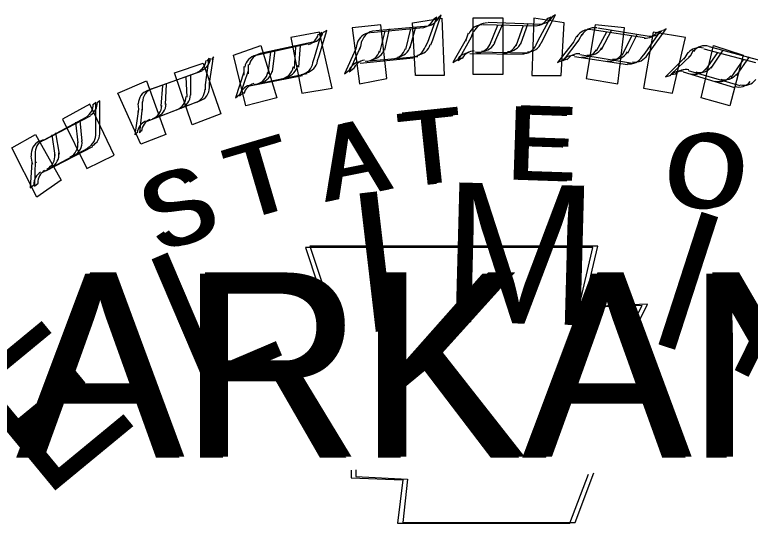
# Model space of a CAD drawing. Extents: x -1771525.9 to -1771483.9, y -422628.9 to -422606.9.
# Drawn here: x -1771500.66 to -1771499.911, y -422625.924 to -422625.405 of the extents above; entities that cross this region are included whole.
import ezdxf

# ---------------------------------------------------------------- set-up
doc = ezdxf.new("R2010")
doc.units = 0
for name, color, linetype in [('Border 2660-Hwy18 - STAMP PRELIM', 7, 'Continuous'), ('Border 2660-Hwy18 - Stamp-ChrisC', 7, 'Continuous'), ('Stamp Charles W', 7, 'Continuous')]:
    doc.layers.add(name, color=color, linetype=linetype)

msp = doc.modelspace()

# ---------------------------------------------------------------- linework, layer by layer
at = {"layer": 'Border 2660-Hwy18 - STAMP PRELIM'}
for p, q in [((-1771500.25546, -422625.41348), (-1771500.22546, -422625.40898)), ((-1771500.25246, -422625.46748), (-1771500.25546, -422625.41348)), ((-1771500.22546, -422625.40898), (-1771500.22316, -422625.46748)), ((-1771500.16316, -422625.40898), (-1771500.19396, -422625.40898)), ((-1771500.19396, -422625.40898), (-1771500.19396, -422625.46598)), ((-1771500.16316, -422625.46598), (-1771500.16316, -422625.40898)), ((-1771500.13166, -422625.40898), (-1771500.13396, -422625.46748)), ((-1771500.10096, -422625.41348), (-1771500.13166, -422625.40898)), ((-1771500.10396, -422625.46748), (-1771500.10096, -422625.41348)), ((-1771500.28766, -422625.41568), (-1771500.31696, -422625.41868)), ((-1771500.31696, -422625.41868), (-1771500.30946, -422625.47568)), ((-1771500.28166, -422625.47048), (-1771500.28766, -422625.41568)), ((-1771500.06946, -422625.41568), (-1771500.07846, -422625.47048)), ((-1771500.03946, -422625.41868), (-1771500.06946, -422625.41568)), ((-1771500.04616, -422625.47568), (-1771500.03946, -422625.41868)), ((-1771500.34996, -422625.42318), (-1771500.37916, -422625.42848)), ((-1771500.37916, -422625.42848), (-1771500.36796, -422625.48548)), ((-1771500.33716, -422625.48018), (-1771500.34996, -422625.42318)), ((-1771500.01016, -422625.42318), (-1771500.01996, -422625.48018)), ((-1771499.97716, -422625.42848), (-1771500.01016, -422625.42318)), ((-1771499.99066, -422625.48548), (-1771499.97716, -422625.42848)), ((-1771500.43766, -422625.44648), (-1771500.40996, -422625.43668)), ((-1771500.40996, -422625.43668), (-1771500.39346, -422625.48998)), ((-1771499.96146, -422625.48998), (-1771499.94866, -422625.43668)), ((-1771499.94866, -422625.43668), (-1771499.91866, -422625.44648)), ((-1771500.42496, -422625.49818), (-1771500.43766, -422625.44648)), ((-1771499.91866, -422625.44648), (-1771499.93216, -422625.49818)), ((-1771500.49766, -422625.46448), (-1771500.46846, -422625.45468)), ((-1771500.46846, -422625.45468), (-1771500.45046, -422625.50648)), ((-1771500.47966, -422625.51768), (-1771500.49766, -422625.46448)), ((-1771500.19396, -422625.46598), (-1771500.16316, -422625.46598)), ((-1771500.55546, -422625.48548), (-1771500.52616, -422625.47268)), ((-1771500.52616, -422625.47268), (-1771500.50666, -422625.52748)), ((-1771500.30946, -422625.47568), (-1771500.28166, -422625.47048)), ((-1771500.22316, -422625.46748), (-1771500.25246, -422625.46748)), ((-1771500.13396, -422625.46748), (-1771500.10396, -422625.46748)), ((-1771500.07846, -422625.47048), (-1771500.04616, -422625.47568)), ((-1771500.36796, -422625.48548), (-1771500.33716, -422625.48018)), ((-1771500.01996, -422625.48018), (-1771499.99066, -422625.48548)), ((-1771500.53216, -422625.53718), (-1771500.55546, -422625.48548)), ((-1771500.58396, -422625.49668), (-1771500.61166, -422625.51168)), ((-1771500.55916, -422625.54848), (-1771500.58396, -422625.49668)), ((-1771500.39346, -422625.48998), (-1771500.42496, -422625.49818)), ((-1771499.93216, -422625.49818), (-1771499.96146, -422625.48998)), ((-1771500.61166, -422625.51168), (-1771500.58696, -422625.56198)), ((-1771500.45046, -422625.50648), (-1771500.47966, -422625.51768)), ((-1771500.66346, -422625.54098), (-1771500.63946, -422625.52748)), ((-1771500.63946, -422625.52748), (-1771500.61316, -422625.57398)), ((-1771500.50666, -422625.52748), (-1771500.53216, -422625.53718)), ((-1771500.63796, -422625.59118), (-1771500.66346, -422625.54098)), ((-1771500.58696, -422625.56198), (-1771500.55916, -422625.54848)), ((-1771500.61316, -422625.57398), (-1771500.63796, -422625.59118))]:
    msp.add_line(p, q, dxfattribs=at)
at = {"layer": 'Border 2660-Hwy18 - Stamp-ChrisC'}
for p, q in [((-1771500.23972, -422625.43323), (-1771500.23072, -422625.40773)), ((-1771500.23072, -422625.40773), (-1771500.23372, -422625.41003)), ((-1771500.12722, -422625.43173), (-1771500.11452, -422625.40773)), ((-1771500.11452, -422625.40773), (-1771500.11752, -422625.40923)), ((-1771500.29822, -422625.42353), (-1771500.24422, -422625.41823)), ((-1771500.28852, -422625.44373), (-1771500.28322, -422625.42203)), ((-1771500.26222, -422625.44073), (-1771500.25702, -422625.41973)), ((-1771500.18352, -422625.41523), (-1771500.12952, -422625.41673)), ((-1771500.17672, -422625.43623), (-1771500.16852, -422625.41603)), ((-1771500.14972, -422625.43703), (-1771500.14222, -422625.41603)), ((-1771500.07252, -422625.42053), (-1771500.01922, -422625.42873)), ((-1771500.01852, -422625.44453), (-1771500.00272, -422625.42203)), ((-1771500.00272, -422625.42203), (-1771500.00572, -422625.42353)), ((-1771500.35522, -422625.44903), (-1771500.34772, -422625.42353)), ((-1771500.34772, -422625.42353), (-1771500.35072, -422625.42573)), ((-1771500.19852, -422625.42423), (-1771500.20072, -422625.43023)), ((-1771500.08822, -422625.42723), (-1771500.09122, -422625.43323)), ((-1771500.06802, -422625.44223), (-1771500.05752, -422625.42273)), ((-1771500.04172, -422625.44673), (-1771500.03202, -422625.42723)), ((-1771500.41452, -422625.44673), (-1771500.36122, -422625.43473)), ((-1771500.31172, -422625.43403), (-1771500.31322, -422625.44003)), ((-1771500.24202, -422625.43773), (-1771500.23972, -422625.43323)), ((-1771500.20072, -422625.43023), (-1771500.21422, -422625.45423)), ((-1771500.20072, -422625.43023), (-1771500.20152, -422625.43253)), ((-1771500.12952, -422625.43623), (-1771500.12722, -422625.43173)), ((-1771500.09122, -422625.43323), (-1771500.10772, -422625.45423)), ((-1771500.09122, -422625.43323), (-1771500.09202, -422625.43473)), ((-1771500.40252, -422625.46553), (-1771500.39952, -422625.44303)), ((-1771500.37552, -422625.46023), (-1771500.37402, -422625.43853)), ((-1771500.31322, -422625.44003), (-1771500.32452, -422625.46553)), ((-1771500.31322, -422625.44003), (-1771500.31402, -422625.44223)), ((-1771500.02152, -422625.44823), (-1771500.01852, -422625.44453)), ((-1771499.97502, -422625.44373), (-1771499.97802, -422625.44903)), ((-1771499.95852, -422625.44003), (-1771499.90602, -422625.45423)), ((-1771499.95702, -422625.46173), (-1771499.94422, -422625.44373)), ((-1771500.46622, -422625.47673), (-1771500.46252, -422625.44973)), ((-1771500.46252, -422625.44973), (-1771500.46472, -422625.45273)), ((-1771500.35672, -422625.45423), (-1771500.35522, -422625.44903)), ((-1771500.25472, -422625.44973), (-1771500.30872, -422625.45503)), ((-1771500.21422, -422625.45423), (-1771500.20972, -422625.45123)), ((-1771500.14222, -422625.44603), (-1771500.19702, -422625.44523)), ((-1771500.10772, -422625.45423), (-1771500.10322, -422625.45203)), ((-1771500.03652, -422625.45653), (-1771500.09052, -422625.44823)), ((-1771499.97802, -422625.44903), (-1771499.99752, -422625.46853)), ((-1771499.97802, -422625.44903), (-1771499.97952, -422625.45053)), ((-1771499.93072, -422625.46923), (-1771499.91802, -422625.45053)), ((-1771500.42722, -422625.45803), (-1771500.42722, -422625.46403)), ((-1771500.52552, -422625.48273), (-1771500.47372, -422625.46403)), ((-1771500.42722, -422625.46403), (-1771500.43552, -422625.49023)), ((-1771500.42722, -422625.46403), (-1771500.42722, -422625.46703)), ((-1771500.32452, -422625.46553), (-1771500.32002, -422625.46173)), ((-1771499.99752, -422625.46853), (-1771499.99222, -422625.46703)), ((-1771499.92702, -422625.47973), (-1771499.97952, -422625.46403)), ((-1771500.48502, -422625.48953), (-1771500.48572, -422625.46853)), ((-1771500.36722, -422625.46773), (-1771500.42122, -422625.47823)), ((-1771500.51122, -422625.49853), (-1771500.50972, -422625.47753)), ((-1771500.46622, -422625.48203), (-1771500.46622, -422625.47673)), ((-1771500.43552, -422625.49023), (-1771500.43172, -422625.48653)), ((-1771500.57802, -422625.49473), (-1771500.58022, -422625.49703)), ((-1771500.57802, -422625.52103), (-1771500.57802, -422625.49473)), ((-1771500.53522, -422625.49623), (-1771500.53452, -422625.50153)), ((-1771500.47602, -422625.49473), (-1771500.52772, -422625.51503)), ((-1771500.53452, -422625.50153), (-1771500.53822, -422625.52773)), ((-1771500.53452, -422625.50153), (-1771500.53522, -422625.50453)), ((-1771500.63502, -422625.53523), (-1771500.58772, -422625.50973)), ((-1771500.59602, -422625.53603), (-1771500.59822, -422625.51503)), ((-1771500.57802, -422625.52623), (-1771500.57802, -422625.52103)), ((-1771500.53822, -422625.52773), (-1771500.53522, -422625.52473)), ((-1771500.61922, -422625.54873), (-1771500.62222, -422625.52773)), ((-1771500.58552, -422625.54123), (-1771500.63352, -422625.56673)), ((-1771500.64402, -422625.54953), (-1771500.64322, -422625.55553)), ((-1771500.64322, -422625.55553), (-1771500.64472, -422625.58173)), ((-1771500.64322, -422625.55553), (-1771500.64252, -422625.55773)), ((-1771500.64472, -422625.58173), (-1771500.64102, -422625.57873))]:
    msp.add_line(p, q, dxfattribs=at)
for points in [[(-1771500.36422, -422625.64253), (-1771500.33872, -422625.71973)], [(-1771500.03502, -422625.72873), (-1771500.02152, -422625.70173), (-1771500.08602, -422625.70403), (-1771500.07172, -422625.64253), (-1771500.36422, -422625.64253)], [(-1771500.31772, -422625.86973), (-1771500.31772, -422625.87723), (-1771500.26522, -422625.87953), (-1771500.27052, -422625.92373), (-1771500.09502, -422625.92373), (-1771500.07622, -422625.87353)]]:
    msp.add_lwpolyline(points, dxfattribs=at)
for centre, start, end in [((-1771500.24732, -422625.40402), 279.92492, 338.71276), ((-1771500.13068, -422625.40198), 273.42361, 332.21146), ((-1771500.18436, -422625.4305), 89.16284, 157.53681), ((-1771500.07533, -422625.43541), 81.42307, 149.79704), ((-1771500.36558, -422625.42147), 286.27006, 345.0579), ((-1771500.29743, -422625.43844), 95.66414, 164.03812), ((-1771500.0183, -422625.41438), 265.68385, 324.47169), ((-1771500.19006, -422625.42956), 269.16284, 337.53681), ((-1771500.16363, -422625.43005), 269.16284, 337.53681), ((-1771500.14309, -422625.43029), 269.16284, 337.53681), ((-1771500.30319, -422625.43815), 275.66414, 344.03812), ((-1771500.27687, -422625.43564), 275.66414, 344.03812), ((-1771500.25645, -422625.43355), 275.66414, 344.03812), ((-1771500.19678, -422625.45881), 93.42361, 152.21146), ((-1771500.08085, -422625.43371), 261.42307, 329.79704), ((-1771499.96305, -422625.45372), 73.99093, 142.3649), ((-1771500.48027, -422625.45025), 294.83706, 353.62491), ((-1771500.41158, -422625.46121), 102.00928, 170.38325), ((-1771500.09144, -422625.46179), 85.68385, 144.47169), ((-1771500.05472, -422625.43776), 261.42307, 329.79704), ((-1771500.03441, -422625.44076), 261.42307, 329.79704), ((-1771500.39146, -422625.45616), 282.00928, 350.38325), ((-1771500.37139, -422625.45183), 282.00928, 350.38325), ((-1771500.30655, -422625.46797), 99.92492, 158.71276), ((-1771500.41734, -422625.46156), 282.00928, 350.38325), ((-1771499.98244, -422625.47779), 78.25171, 137.03955), ((-1771499.9683, -422625.45132), 253.99093, 322.3649), ((-1771499.94292, -422625.45871), 253.99093, 322.3649), ((-1771499.92316, -422625.46432), 253.99093, 322.3649), ((-1771500.48149, -422625.48113), 290.57629, 358.95026), ((-1771500.41739, -422625.49157), 106.27006, 165.0579), ((-1771500.51984, -422625.4964), 110.57629, 178.95026), ((-1771500.50069, -422625.4884), 290.57629, 358.95026), ((-1771500.59536, -422625.49682), 301.95449, 0.74233), ((-1771500.52548, -422625.4976), 290.57629, 358.95026), ((-1771500.52106, -422625.52728), 114.83706, 173.62491), ((-1771500.59275, -422625.52762), 297.69371, 6.06769), ((-1771500.62891, -422625.54751), 117.69371, 186.06769), ((-1771500.6109, -422625.53721), 297.69371, 6.06769), ((-1771500.63436, -422625.54941), 297.69371, 6.06769), ((-1771500.62629, -422625.57831), 121.95449, 180.74233)]:
    msp.add_arc(centre, 0.01481, start, end, dxfattribs=at)
at = {"layer": 'Stamp Charles W'}
for p, q in [((-1771500.23477, -422625.43113), (-1771500.22618, -422625.40535)), ((-1771500.22618, -422625.40535), (-1771500.22904, -422625.40822)), ((-1771500.12212, -422625.43017), (-1771500.10971, -422625.40535)), ((-1771500.10971, -422625.40535), (-1771500.11258, -422625.40726)), ((-1771500.17844, -422625.41299), (-1771500.12403, -422625.4149)), ((-1771500.17176, -422625.43399), (-1771500.16317, -422625.41394)), ((-1771500.14503, -422625.43494), (-1771500.1374, -422625.41394)), ((-1771500.35028, -422625.44735), (-1771500.34264, -422625.42158)), ((-1771500.34264, -422625.42158), (-1771500.34646, -422625.42349)), ((-1771500.293, -422625.42158), (-1771500.23954, -422625.41681)), ((-1771500.28345, -422625.44163), (-1771500.27868, -422625.41967)), ((-1771500.25768, -422625.43876), (-1771500.25195, -422625.41776)), ((-1771500.06675, -422625.41872), (-1771500.01425, -422625.42731)), ((-1771500.06293, -422625.44067), (-1771500.05243, -422625.42063)), ((-1771500.01329, -422625.44258), (-1771499.99707, -422625.41967)), ((-1771499.99707, -422625.41967), (-1771499.99993, -422625.42158)), ((-1771500.19563, -422625.42826), (-1771500.20899, -422625.45213)), ((-1771500.19563, -422625.42826), (-1771500.19658, -422625.43017)), ((-1771500.19372, -422625.42253), (-1771500.19563, -422625.42826)), ((-1771500.08298, -422625.4254), (-1771500.08585, -422625.43113)), ((-1771500.03621, -422625.44449), (-1771500.02666, -422625.4254)), ((-1771500.41042, -422625.44449), (-1771500.35696, -422625.43304)), ((-1771500.37128, -422625.45881), (-1771500.36937, -422625.43685)), ((-1771500.30732, -422625.43208), (-1771500.30827, -422625.43781)), ((-1771500.23668, -422625.4359), (-1771500.23477, -422625.43113)), ((-1771500.12403, -422625.43399), (-1771500.12212, -422625.43017)), ((-1771500.08585, -422625.43113), (-1771500.10207, -422625.45213)), ((-1771500.08585, -422625.43113), (-1771500.0868, -422625.43304)), ((-1771500.39801, -422625.46358), (-1771500.39514, -422625.44163)), ((-1771500.30827, -422625.43781), (-1771500.31973, -422625.46358)), ((-1771500.30827, -422625.43781), (-1771500.30923, -422625.44067)), ((-1771500.1374, -422625.44449), (-1771500.19181, -422625.44354)), ((-1771500.01616, -422625.4464), (-1771500.01329, -422625.44258)), ((-1771499.96938, -422625.44163), (-1771499.97225, -422625.44735)), ((-1771499.95315, -422625.43781), (-1771499.90065, -422625.45213)), ((-1771499.95124, -422625.45977), (-1771499.93883, -422625.44163)), ((-1771500.46197, -422625.47504), (-1771500.45815, -422625.44831)), ((-1771500.45815, -422625.44831), (-1771500.46006, -422625.45117)), ((-1771500.35219, -422625.45213), (-1771500.35028, -422625.44735)), ((-1771500.25004, -422625.44831), (-1771500.3035, -422625.45308)), ((-1771500.20899, -422625.45213), (-1771500.20517, -422625.44926)), ((-1771500.10207, -422625.45213), (-1771500.09826, -422625.45022)), ((-1771500.03143, -422625.45499), (-1771500.08489, -422625.4464)), ((-1771499.97225, -422625.44735), (-1771499.99229, -422625.46645)), ((-1771499.97225, -422625.44735), (-1771499.97415, -422625.44831)), ((-1771499.92547, -422625.4674), (-1771499.9121, -422625.44831)), ((-1771500.42283, -422625.45595), (-1771500.42283, -422625.46263)), ((-1771500.31973, -422625.46358), (-1771500.31496, -422625.45977)), ((-1771500.52116, -422625.48077), (-1771500.46961, -422625.46263)), ((-1771500.48106, -422625.48745), (-1771500.48106, -422625.46645)), ((-1771500.42283, -422625.46263), (-1771500.43142, -422625.4884)), ((-1771500.42283, -422625.46263), (-1771500.42283, -422625.46549)), ((-1771500.36269, -422625.46549), (-1771500.4171, -422625.47695)), ((-1771499.99229, -422625.46645), (-1771499.98656, -422625.46549)), ((-1771499.92165, -422625.4779), (-1771499.97415, -422625.46263)), ((-1771500.50684, -422625.497), (-1771500.50588, -422625.47599)), ((-1771500.46197, -422625.47981), (-1771500.46197, -422625.47504)), ((-1771500.43142, -422625.4884), (-1771500.4276, -422625.48459)), ((-1771500.57366, -422625.49318), (-1771500.57652, -422625.49509)), ((-1771500.57366, -422625.51895), (-1771500.57366, -422625.49318)), ((-1771500.5307, -422625.49413), (-1771500.5307, -422625.49986)), ((-1771500.47151, -422625.49318), (-1771500.52306, -422625.51322)), ((-1771500.5307, -422625.49986), (-1771500.53357, -422625.52563)), ((-1771500.5307, -422625.49986), (-1771500.5307, -422625.50272)), ((-1771500.63094, -422625.53327), (-1771500.58321, -422625.50845)), ((-1771500.5918, -422625.53423), (-1771500.59371, -422625.51322)), ((-1771500.57366, -422625.52468), (-1771500.57366, -422625.51895)), ((-1771500.61471, -422625.54759), (-1771500.61853, -422625.52563)), ((-1771500.53357, -422625.52563), (-1771500.5307, -422625.52277)), ((-1771500.5813, -422625.53995), (-1771500.62903, -422625.56477)), ((-1771500.63953, -422625.54759), (-1771500.63953, -422625.55427)), ((-1771500.63953, -422625.55427), (-1771500.64048, -422625.58005)), ((-1771500.63953, -422625.55427), (-1771500.63857, -422625.55618)), ((-1771500.64048, -422625.58005), (-1771500.63667, -422625.57718))]:
    msp.add_line(p, q, dxfattribs=at)
for points in [[(-1771500.35982, -422625.64114), (-1771500.33405, -422625.71847)], [(-1771500.02952, -422625.72802), (-1771500.01616, -422625.70033), (-1771500.08107, -422625.70319), (-1771500.06675, -422625.64114), (-1771500.35982, -422625.64114)], [(-1771500.31305, -422625.8693), (-1771500.31305, -422625.87598), (-1771500.26054, -422625.87885), (-1771500.26532, -422625.92276), (-1771500.08966, -422625.92276), (-1771500.07057, -422625.87216)]]:
    msp.add_lwpolyline(points, dxfattribs=at)
for centre, start, end in [((-1771500.12544, -422625.40002), 273.42361, 332.21146), ((-1771500.24234, -422625.40206), 279.92492, 338.71276), ((-1771500.17924, -422625.4286), 89.16284, 157.53681), ((-1771500.29255, -422625.43655), 95.66414, 164.03812), ((-1771500.06997, -422625.43352), 81.42307, 149.79704), ((-1771500.01281, -422625.41245), 265.68385, 324.47169), ((-1771500.36086, -422625.41955), 286.27006, 345.0579), ((-1771500.25148, -422625.43166), 275.66414, 344.03812), ((-1771500.18495, -422625.42766), 269.16284, 337.53681), ((-1771500.15846, -422625.42815), 269.16284, 337.53681), ((-1771500.13788, -422625.42839), 269.16284, 337.53681), ((-1771499.95743, -422625.45187), 73.99093, 142.3649), ((-1771500.29833, -422625.43627), 275.66414, 344.03812), ((-1771500.27195, -422625.43375), 275.66414, 344.03812), ((-1771500.19168, -422625.45697), 93.42361, 152.21146), ((-1771500.07549, -422625.43182), 261.42307, 329.79704), ((-1771500.04931, -422625.43587), 261.42307, 329.79704), ((-1771500.47581, -422625.44839), 294.83706, 353.62491), ((-1771500.40696, -422625.45938), 102.00928, 170.38325), ((-1771500.3017, -422625.46615), 99.92492, 158.71276), ((-1771500.08611, -422625.45996), 85.68385, 144.47169), ((-1771500.02895, -422625.43888), 261.42307, 329.79704), ((-1771500.3868, -422625.45432), 282.00928, 350.38325), ((-1771500.36668, -422625.44997), 282.00928, 350.38325), ((-1771499.96269, -422625.44947), 253.99093, 322.3649), ((-1771500.41273, -422625.45973), 282.00928, 350.38325), ((-1771499.97686, -422625.476), 78.25171, 137.03955), ((-1771499.93725, -422625.45688), 253.99093, 322.3649), ((-1771499.91746, -422625.46249), 253.99093, 322.3649), ((-1771500.51546, -422625.49464), 110.57629, 178.95026), ((-1771500.47703, -422625.47934), 290.57629, 358.95026), ((-1771500.41278, -422625.4898), 106.27006, 165.0579), ((-1771500.49628, -422625.48663), 290.57629, 358.95026), ((-1771500.59116, -422625.49507), 301.95449, 0.74233), ((-1771500.52112, -422625.49585), 290.57629, 358.95026), ((-1771500.51669, -422625.5256), 114.83706, 173.62491), ((-1771500.58854, -422625.52593), 297.69371, 6.06769), ((-1771500.62477, -422625.54588), 117.69371, 186.06769), ((-1771500.60673, -422625.53555), 297.69371, 6.06769), ((-1771500.63024, -422625.54777), 297.69371, 6.06769), ((-1771500.62215, -422625.57674), 121.95449, 180.74233)]:
    msp.add_arc(centre, 0.01484, start, end, dxfattribs=at)

# ---------------------------------------------------------------- texts
at = {"layer": 'Border 2660-Hwy18 - STAMP PRELIM'}
for s, rotation, p in [('M', 358.46666, (-1771500.22696, -422625.71798)), ('I', 6.67523, (-1771500.31016, -422625.73068)), ('I', 342.04953, (-1771500.02146, -422625.73598)), ('N', 333.84096, (-1771499.94116, -422625.76068)), ('L', 23.09236, (-1771500.47966, -422625.79148)), ('E', 39.5095, (-1771500.63116, -422625.90018))]:
    msp.add_text(s, height=0.14209, rotation=rotation, dxfattribs=at).set_placement(p)
at = {"layer": 'Border 2660-Hwy18 - Stamp-ChrisC'}
for s, height, rotation, p in [('T', 0.075, 6.02276, (-1771500.26572, -422625.58143)), ('E', 0.07499, 358.07323, (-1771500.16072, -422625.57323)), ('A', 0.075, 11.21318, (-1771500.34452, -422625.59643)), ('O', 0.07498, 350.4515, (-1771500.00402, -422625.59573)), ('T', 0.07499, 16.4036, (-1771500.43152, -422625.61673)), ('S', 0.07499, 21.59401, (-1771500.51402, -422625.64973))]:
    msp.add_text(s, height=height, rotation=rotation, dxfattribs=at).set_placement(p)
msp.add_text('ARKANSAS', height=0.187497, dxfattribs=at).set_placement((-1771500.65952, -422625.85673))
at = {"layer": 'Stamp Charles W'}
for s, height, rotation, p in [('T', 0.07517, 6.02276, (-1771500.26054, -422625.58005)), ('E', 0.07515, 358.07323, (-1771500.15553, -422625.57241)), ('A', 0.07517, 11.21318, (-1771500.33978, -422625.59532)), ('T', 0.07515, 16.4036, (-1771500.42665, -422625.61537)), ('O', 0.07514, 350.4515, (-1771499.99802, -422625.59437)), ('S', 0.07515, 21.59401, (-1771500.50875, -422625.64878))]:
    msp.add_text(s, height=height, rotation=rotation, dxfattribs=at).set_placement(p)
msp.add_text('ARKANSAS', height=0.187911, dxfattribs=at).set_placement((-1771500.6548, -422625.85594))

doc.saveas('drawing.dxf')
